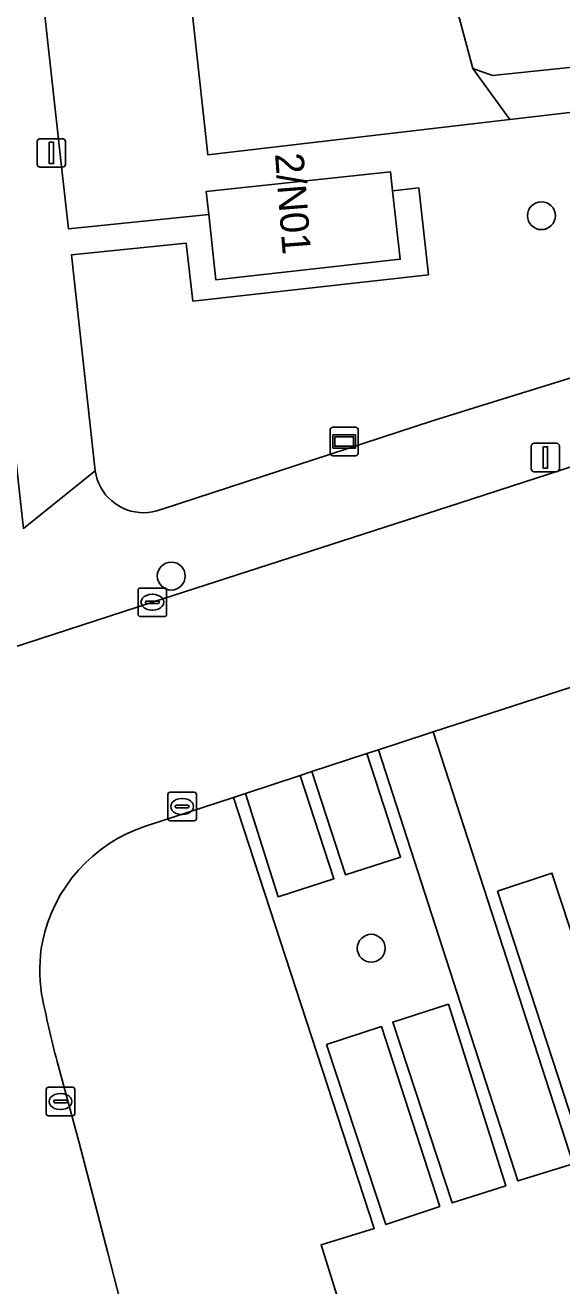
# Model space of a CAD drawing. Extents: x 161248 to 161848, y 384871 to 385383.
# Drawn here: x 161425.69 to 161444.53, y 385046.89 to 385091.12 of the extents above; entities that cross this region are included whole.
import ezdxf

# ---------------------------------------------------------------- set-up
doc = ezdxf.new("R2010")
doc.units = 0
for name, color, linetype in [('IMGEO_Boom', 7, 'Continuous'), ('IMGEO_Groenvoorziening', 7, 'Continuous'), ('IMGEO_Hek', 7, 'Continuous'), ('IMGEO_Kolk', 7, 'Continuous'), ('IMGEO_Lichtmast', 7, 'Continuous'), ('IMGEO_Pand', 7, 'Continuous'), ('IMGEO_Pand_nummerreeks', 7, 'Continuous'), ('IMGEO_Parkeervlak_halfverhard', 7, 'Continuous'), ('IMGEO_Parkeervlak_open', 7, 'Continuous'), ('IMGEO_Rijbaan_lokaal_open', 7, 'Continuous'), ('IMGEO_Verklikker', 7, 'Continuous'), ('IMGEO_Voetpad_open', 7, 'Continuous')]:
    doc.layers.add(name, color=color, linetype=linetype)

msp = doc.modelspace()

# ---------------------------------------------------------------- linework, layer by layer
at = {"layer": 'IMGEO_Boom'}
for centre in [(161443.813, 385084.433), (161430.819, 385071.789), (161437.837, 385058.731)]:
    msp.add_circle(centre, 0.489, dxfattribs=at)
at = {"layer": 'IMGEO_Groenvoorziening'}
for points in [[(161423.135, 385168.705), (161424.044, 385160.38), (161425.338, 385148.53), (161426.244, 385140.237), (161427.548, 385128.296), (161428.464, 385119.908), (161429.745, 385108.177), (161430.517, 385101.115), (161431.628, 385090.94), (161432.106, 385086.565), (161442.398, 385087.77), (161442.697, 385087.805), (161441.4, 385089.603), (161440.759, 385091.997), (161440.609, 385093.05), (161439.577, 385093.264), (161438.834, 385093.495), (161438.183, 385093.977), (161437.632, 385095.831), (161437.566, 385096.339), (161437.043, 385096.328), (161437.101, 385095.788), (161437.332, 385093.631)], [(161484.879, 385092.744), (161470.726, 385091.087), (161442.697, 385087.805), (161442.398, 385087.77), (161432.106, 385086.565), (161431.628, 385090.94), (161430.517, 385101.115), (161429.745, 385108.177), (161428.464, 385119.908), (161427.548, 385128.296), (161426.244, 385140.237), (161425.338, 385148.53), (161424.044, 385160.38), (161423.135, 385168.705)], [(161418.12, 385166.146), (161426.978, 385086.052), (161427.209, 385083.967), (161432.136, 385084.473), (161432.049, 385085.283), (161438.514, 385085.978), (161438.589, 385085.303), (161439.505, 385085.406), (161439.843, 385082.364), (161431.579, 385081.436), (161431.343, 385083.465), (161427.314, 385083.055), (161428.151, 385075.476), (161428.18, 385075.326), (161428.222, 385075.178), (161428.278, 385075.036), (161428.345, 385074.898), (161428.425, 385074.768), (161428.516, 385074.645), (161428.618, 385074.53), (161428.73, 385074.425), (161428.85, 385074.331), (161428.979, 385074.248), (161429.114, 385074.176), (161429.255, 385074.117), (161429.401, 385074.071), (161429.551, 385074.038), (161429.703, 385074.018), (161429.856, 385074.012), (161430.009, 385074.02), (161430.16, 385074.041), (161430.309, 385074.076), (161430.455, 385074.124), (161430.465, 385074.128), (161439.983, 385077.235), (161441.446, 385077.688), (161469.66, 385086.431)]]:
    msp.add_lwpolyline(points, dxfattribs=at)
for points in [[(161465.36, 385092.132), (161465.416, 385092.972), (161465.057, 385094.843), (161464.945, 385095.485), (161442.358, 385092.869), (161441.669, 385092.83), (161440.609, 385093.05), (161440.759, 385091.997), (161441.4, 385089.603), (161442.1, 385089.349), (161451.889, 385090.373), (161455.584, 385090.791)], [(161484.879, 385092.744), (161484.766, 385094.364), (161476.925, 385093.612), (161472.849, 385093.601), (161465.416, 385092.972), (161465.36, 385092.132), (161455.584, 385090.791), (161451.889, 385090.373), (161442.1, 385089.349), (161441.4, 385089.603), (161442.697, 385087.805), (161470.726, 385091.087)]]:
    msp.add_lwpolyline(points, close=True, dxfattribs=at)
at = {"layer": 'IMGEO_Hek'}
for points in [[(161431.628, 385090.94), (161430.517, 385101.115)], [(161432.106, 385086.565), (161431.628, 385090.94)], [(161470.726, 385091.087), (161442.697, 385087.805)], [(161442.398, 385087.77), (161432.106, 385086.565)], [(161442.697, 385087.805), (161442.398, 385087.77)]]:
    msp.add_lwpolyline(points, dxfattribs=at)
at = {"layer": 'IMGEO_Kolk'}
for p, q in [((161429.656, 385070.444), (161429.656, 385071.296)), ((161429.731, 385071.37), (161430.583, 385071.37)), ((161430.144, 385071.15), (161430.169, 385071.15)), ((161430.657, 385071.296), (161430.657, 385070.444)), ((161429.915, 385070.864), (161429.915, 385070.876)), ((161430.353, 385070.827), (161429.955, 385070.827)), ((161429.958, 385070.913), (161430.356, 385070.913)), ((161430.167, 385070.59), (161430.142, 385070.59)), ((161430.399, 385070.876), (161430.399, 385070.864)), ((161430.583, 385070.37), (161429.731, 385070.37)), ((161430.701, 385063.277), (161430.701, 385064.129)), ((161430.776, 385064.203), (161431.628, 385064.203)), ((161431.189, 385063.983), (161431.214, 385063.983)), ((161431.702, 385064.129), (161431.702, 385063.277)), ((161430.96, 385063.697), (161430.96, 385063.709)), ((161431.398, 385063.66), (161431, 385063.66)), ((161431.003, 385063.746), (161431.401, 385063.746)), ((161431.444, 385063.709), (161431.444, 385063.697)), ((161431.628, 385063.203), (161430.776, 385063.203)), ((161431.212, 385063.423), (161431.187, 385063.423)), ((161426.433, 385052.926), (161426.433, 385053.778)), ((161426.508, 385053.852), (161427.36, 385053.852)), ((161427.434, 385053.778), (161427.434, 385052.926)), ((161426.692, 385053.346), (161426.692, 385053.358)), ((161427.13, 385053.309), (161426.732, 385053.309)), ((161426.735, 385053.395), (161427.133, 385053.395)), ((161426.921, 385053.632), (161426.946, 385053.632)), ((161427.176, 385053.358), (161427.176, 385053.346)), ((161427.36, 385052.852), (161426.508, 385052.852)), ((161426.944, 385053.072), (161426.919, 385053.072))]:
    msp.add_line(p, q, dxfattribs=at)
for points in [[(161429.656, 385070.444), (161429.656, 385071.296)], [(161429.731, 385071.37), (161430.583, 385071.37)], [(161430.657, 385071.296), (161430.657, 385070.444)], [(161430.583, 385070.37), (161429.731, 385070.37)], [(161430.701, 385063.277), (161430.701, 385064.129)], [(161430.776, 385064.203), (161431.628, 385064.203)], [(161431.702, 385064.129), (161431.702, 385063.277)], [(161431.628, 385063.203), (161430.776, 385063.203)], [(161426.433, 385052.926), (161426.433, 385053.778)], [(161426.508, 385053.852), (161427.36, 385053.852)], [(161427.434, 385053.778), (161427.434, 385052.926)], [(161427.36, 385052.852), (161426.508, 385052.852)]]:
    msp.add_lwpolyline(points, dxfattribs=at)
for centre, radius, start, end in [((161429.733, 385071.294), 0.0765, 91.552, 178.448), ((161429.733, 385071.294), 0.0765, 91.552, 178.448), ((161430.581, 385071.294), 0.0765, 1.552, 88.448), ((161430.581, 385071.294), 0.0765, 1.552, 88.448), ((161429.955, 385070.873), 0.0403, 85.8775, 175.7526), ((161429.952, 385070.863), 0.0366, 178.938, 274.7102), ((161430.356, 385070.87), 0.043, 264.8664, 352.4533), ((161430.36, 385070.875), 0.0386, 1.7309, 96.639), ((161429.733, 385070.446), 0.0765, 181.552, 268.448), ((161429.733, 385070.446), 0.0765, 181.552, 268.448), ((161430.581, 385070.446), 0.0765, 271.552, 358.448), ((161430.581, 385070.446), 0.0765, 271.552, 358.448), ((161430.778, 385064.127), 0.0765, 91.552, 178.448), ((161430.778, 385064.127), 0.0765, 91.552, 178.448), ((161431.626, 385064.127), 0.0765, 1.552, 88.448), ((161431.626, 385064.127), 0.0765, 1.552, 88.448), ((161431, 385063.706), 0.0403, 85.8775, 175.7526), ((161430.997, 385063.696), 0.0366, 178.938, 274.7102), ((161431.401, 385063.703), 0.043, 264.8664, 352.4533), ((161431.405, 385063.708), 0.0386, 1.7309, 96.639), ((161430.778, 385063.279), 0.0765, 181.552, 268.448), ((161430.778, 385063.279), 0.0765, 181.552, 268.448), ((161431.626, 385063.279), 0.0765, 271.552, 358.448), ((161431.626, 385063.279), 0.0765, 271.552, 358.448), ((161426.51, 385053.776), 0.0765, 91.552, 178.448), ((161426.51, 385053.776), 0.0765, 91.552, 178.448), ((161427.358, 385053.776), 0.0765, 1.552, 88.448), ((161427.358, 385053.776), 0.0765, 1.552, 88.448), ((161426.732, 385053.355), 0.0403, 85.8775, 175.7526), ((161426.729, 385053.345), 0.0366, 178.938, 274.7102), ((161427.133, 385053.352), 0.043, 264.8664, 352.4533), ((161427.137, 385053.357), 0.0386, 1.7309, 96.639), ((161426.51, 385052.928), 0.0765, 181.552, 268.448), ((161426.51, 385052.928), 0.0765, 181.552, 268.448), ((161427.358, 385052.928), 0.0765, 271.552, 358.448), ((161427.358, 385052.928), 0.0765, 271.552, 358.448)]:
    msp.add_arc(centre, radius, start, end, dxfattribs=at)
for centre, major_axis, ratio, start_param, end_param in [((161430.143, 385070.87), (-0.387, 0.002), 0.722429, 4.712389, 7.853982), ((161430.168, 385070.87), (-0.39, 0.002), 0.717154, 1.570796, 4.712389), ((161431.188, 385063.703), (-0.387, 0.002), 0.722429, 4.712389, 7.853982), ((161431.213, 385063.703), (-0.39, 0.002), 0.717154, 1.570796, 4.712389), ((161426.92, 385053.352), (-0.387, 0.002), 0.722429, 4.712389, 7.853982), ((161426.945, 385053.352), (-0.39, 0.002), 0.717154, 1.570796, 4.712389)]:
    msp.add_ellipse(centre, major_axis=major_axis, ratio=ratio, start_param=start_param, end_param=end_param, dxfattribs=at)
at = {"layer": 'IMGEO_Lichtmast'}
for p, q in [((161426.116, 385086.235), (161426.116, 385087.035)), ((161426.116, 385087.035), (161426.116, 385086.235)), ((161426.216, 385087.135), (161427.006, 385087.135)), ((161427.006, 385087.135), (161426.216, 385087.135)), ((161427.106, 385087.035), (161427.106, 385086.235)), ((161427.106, 385086.235), (161427.106, 385087.035)), ((161427.006, 385086.135), (161426.216, 385086.135)), ((161426.216, 385086.135), (161427.006, 385086.135)), ((161443.455, 385075.55), (161443.455, 385076.35)), ((161443.455, 385076.35), (161443.455, 385075.55)), ((161443.555, 385076.45), (161444.345, 385076.45)), ((161444.345, 385076.45), (161443.555, 385076.45)), ((161444.445, 385076.35), (161444.445, 385075.55)), ((161444.445, 385075.55), (161444.445, 385076.35)), ((161444.345, 385075.45), (161443.555, 385075.45)), ((161443.555, 385075.45), (161444.345, 385075.45))]:
    msp.add_line(p, q, dxfattribs=at)
for points in [[(161426.536, 385087.01), (161426.686, 385087.01), (161426.686, 385086.26), (161426.536, 385086.26), (161426.536, 385087.01)], [(161443.875, 385076.325), (161444.025, 385076.325), (161444.025, 385075.575), (161443.875, 385075.575), (161443.875, 385076.325)]]:
    msp.add_lwpolyline(points, dxfattribs=at)
for centre, start, end in [((161426.216, 385087.035), 90, 180), ((161426.216, 385087.035), 90, 180), ((161427.006, 385087.035), 0, 90), ((161427.006, 385087.035), 360, 90), ((161426.216, 385086.235), 180, 270), ((161426.216, 385086.235), 180, 270), ((161427.006, 385086.235), 270, 0), ((161427.006, 385086.235), 270, 0), ((161443.555, 385076.35), 90, 180), ((161443.555, 385076.35), 90, 180), ((161444.345, 385076.35), 0, 90), ((161444.345, 385076.35), 360, 90), ((161443.555, 385075.55), 180, 270), ((161443.555, 385075.55), 180, 270), ((161444.345, 385075.55), 270, 0), ((161444.345, 385075.55), 270, 0)]:
    msp.add_arc(centre, 0.1, start, end, dxfattribs=at)
at = {"layer": 'IMGEO_Pand'}
msp.add_lwpolyline([(161432.136, 385084.473), (161432.384, 385082.18), (161438.857, 385082.906), (161438.589, 385085.303), (161438.514, 385085.978), (161432.049, 385085.283)], close=True, dxfattribs=at)
at = {"layer": 'IMGEO_Parkeervlak_halfverhard'}
for points in [[(161440.008, 385066.32), (161438.843, 385065.943), (161438.09, 385065.696), (161442.979, 385050.566), (161444.92, 385051.172)], [(161437.679, 385065.561), (161435.752, 385064.929), (161436.929, 385061.31), (161438.864, 385061.926)], [(161435.34, 385064.794), (161433.427, 385064.166), (161434.573, 385060.54), (161436.528, 385061.172)], [(161442.268, 385060.735), (161445.351, 385051.317), (161447.293, 385051.92), (161444.181, 385061.367)], [(161440.551, 385056.763), (161438.594, 385056.141), (161440.673, 385049.796), (161442.559, 385050.397)], [(161440.248, 385049.664), (161438.197, 385055.98), (161436.273, 385055.35), (161438.349, 385049.034)]]:
    msp.add_lwpolyline(points, close=True, dxfattribs=at)
for points in [[(161436.076, 385048.327), (161437.935, 385048.896), (161432.999, 385064.025), (161429.917, 385063.014)], [(161426.814, 385054.752), (161427.573, 385051.945), (161428.592, 385048.045), (161429.019, 385046.404)], [(161436.574, 385042.22), (161437.674, 385042.556), (161437.861, 385042.614), (161436.076, 385048.327)]]:
    msp.add_lwpolyline(points, dxfattribs=at)
for centre, radius, start, end in [((161431.623, 385057.848), 5.441, 108.2773, 168.3333), ((161431.714, 385057.951), 5.51, 169.5708, 188.6054), ((161467.86, 385065.477), 42.424, 191.3527, 194.6436)]:
    msp.add_arc(centre, radius, start, end, dxfattribs=at)
at = {"layer": 'IMGEO_Parkeervlak_open'}
msp.add_lwpolyline([(161471.347, 385076.545), (161456.059, 385071.513), (161440.008, 385066.32), (161444.92, 385051.172), (161442.979, 385050.566), (161438.09, 385065.696), (161437.679, 385065.561), (161438.864, 385061.926), (161436.929, 385061.31), (161435.752, 385064.929), (161435.34, 385064.794), (161436.528, 385061.172), (161434.573, 385060.54), (161433.427, 385064.166), (161432.999, 385064.025), (161437.935, 385048.896), (161436.076, 385048.327), (161437.861, 385042.614), (161439.031, 385042.98), (161452.512, 385047.336), (161470.434, 385053.161), (161465.544, 385068.314)], dxfattribs=at)
for points in [[(161442.268, 385060.735), (161444.181, 385061.367), (161447.293, 385051.92), (161445.351, 385051.317)], [(161440.551, 385056.763), (161442.559, 385050.397), (161440.673, 385049.796), (161438.594, 385056.141)], [(161440.248, 385049.664), (161438.349, 385049.034), (161436.273, 385055.35), (161438.197, 385055.98)]]:
    msp.add_lwpolyline(points, close=True, dxfattribs=at)
at = {"layer": 'IMGEO_Rijbaan_lokaal_open'}
for points in [[(161469.526, 385083.633), (161460.453, 385080.682), (161440.926, 385074.344), (161430.157, 385070.87), (161417.274, 385066.689), (161410.636, 385064.527), (161397.711, 385060.359), (161391.558, 385058.354), (161387.979, 385057.181), (161382.273, 385055.346), (161378.684, 385054.165), (161378.461, 385054.101), (161373.432, 385052.501), (161369.85, 385051.335), (161364.64, 385049.653), (161361.05, 385048.512), (161359.276, 385047.937), (161358.951, 385047.777), (161358.438, 385047.57), (161357.909, 385047.41), (161338.624, 385041.3)], [(161432.999, 385064.025), (161433.427, 385064.166), (161435.34, 385064.794), (161435.752, 385064.929), (161437.679, 385065.561), (161438.09, 385065.696), (161438.843, 385065.943), (161440.008, 385066.32), (161456.059, 385071.513), (161471.347, 385076.545)], [(161429.917, 385063.014), (161432.999, 385064.025)], [(161429.019, 385046.404), (161428.592, 385048.045), (161427.573, 385051.945), (161426.814, 385054.752)]]:
    msp.add_lwpolyline(points, dxfattribs=at)
for centre, radius, start, end in [((161431.623, 385057.848), 5.441, 108.2773, 168.3333), ((161431.714, 385057.951), 5.51, 169.5708, 188.6054), ((161467.86, 385065.477), 42.424, 191.3527, 194.6436)]:
    msp.add_arc(centre, radius, start, end, dxfattribs=at)
at = {"layer": 'IMGEO_Verklikker'}
for p, q in [((161436.392, 385076.109), (161436.392, 385076.909)), ((161436.392, 385076.909), (161436.392, 385076.109)), ((161436.492, 385077.009), (161437.282, 385077.009)), ((161437.282, 385077.009), (161436.492, 385077.009)), ((161437.382, 385076.909), (161437.382, 385076.109)), ((161437.382, 385076.109), (161437.382, 385076.909)), ((161437.282, 385076.009), (161436.492, 385076.009)), ((161436.492, 385076.009), (161437.282, 385076.009))]:
    msp.add_line(p, q, dxfattribs=at)
for points in [[(161436.493, 385076.741), (161437.281, 385076.741), (161437.281, 385076.277), (161436.493, 385076.277), (161436.493, 385076.741)], [(161436.558, 385076.676), (161436.558, 385076.342), (161437.216, 385076.342), (161437.216, 385076.676), (161436.558, 385076.676)]]:
    msp.add_lwpolyline(points, dxfattribs=at)
for centre, start, end in [((161436.492, 385076.909), 90, 180), ((161436.492, 385076.909), 90, 180), ((161437.282, 385076.909), 0, 90), ((161437.282, 385076.909), 360, 90), ((161436.492, 385076.109), 180, 270), ((161436.492, 385076.109), 180, 270), ((161437.282, 385076.109), 270, 0), ((161437.282, 385076.109), 270, 0)]:
    msp.add_arc(centre, 0.1, start, end, dxfattribs=at)
at = {"layer": 'IMGEO_Voetpad_open'}
for points in [[(161423.497, 385092.578), (161424.001, 385088.115), (161424.553, 385083.136), (161424.57, 385082.983), (161425.068, 385078.533), (161425.628, 385073.461), (161428.151, 385075.476), (161427.314, 385083.055), (161431.343, 385083.465), (161431.579, 385081.436), (161439.843, 385082.364), (161439.505, 385085.406), (161438.589, 385085.303), (161438.857, 385082.906), (161432.384, 385082.18), (161432.136, 385084.473), (161427.209, 385083.967), (161426.978, 385086.052), (161418.12, 385166.146)], [(161469.66, 385086.431), (161441.446, 385077.688), (161439.983, 385077.235), (161430.465, 385074.128), (161430.455, 385074.124), (161430.309, 385074.076), (161430.16, 385074.041), (161430.009, 385074.02), (161429.856, 385074.012), (161429.703, 385074.018), (161429.551, 385074.038), (161429.401, 385074.071), (161429.255, 385074.117), (161429.114, 385074.176), (161428.979, 385074.248), (161428.85, 385074.331), (161428.73, 385074.425), (161428.618, 385074.53), (161428.516, 385074.645), (161428.425, 385074.768), (161428.345, 385074.898), (161428.278, 385075.036), (161428.222, 385075.178), (161428.18, 385075.326), (161428.151, 385075.476), (161425.628, 385073.461)], [(161417.274, 385066.689), (161430.157, 385070.87), (161440.926, 385074.344), (161460.453, 385080.682), (161469.526, 385083.633)]]:
    msp.add_lwpolyline(points, dxfattribs=at)

# ---------------------------------------------------------------- texts
at = {"layer": 'IMGEO_Pand_nummerreeks'}
msp.add_text('2/N01', height=1, rotation=274.3987, dxfattribs=at).set_placement((161434.459, 385086.601))

doc.saveas('drawing.dxf')
